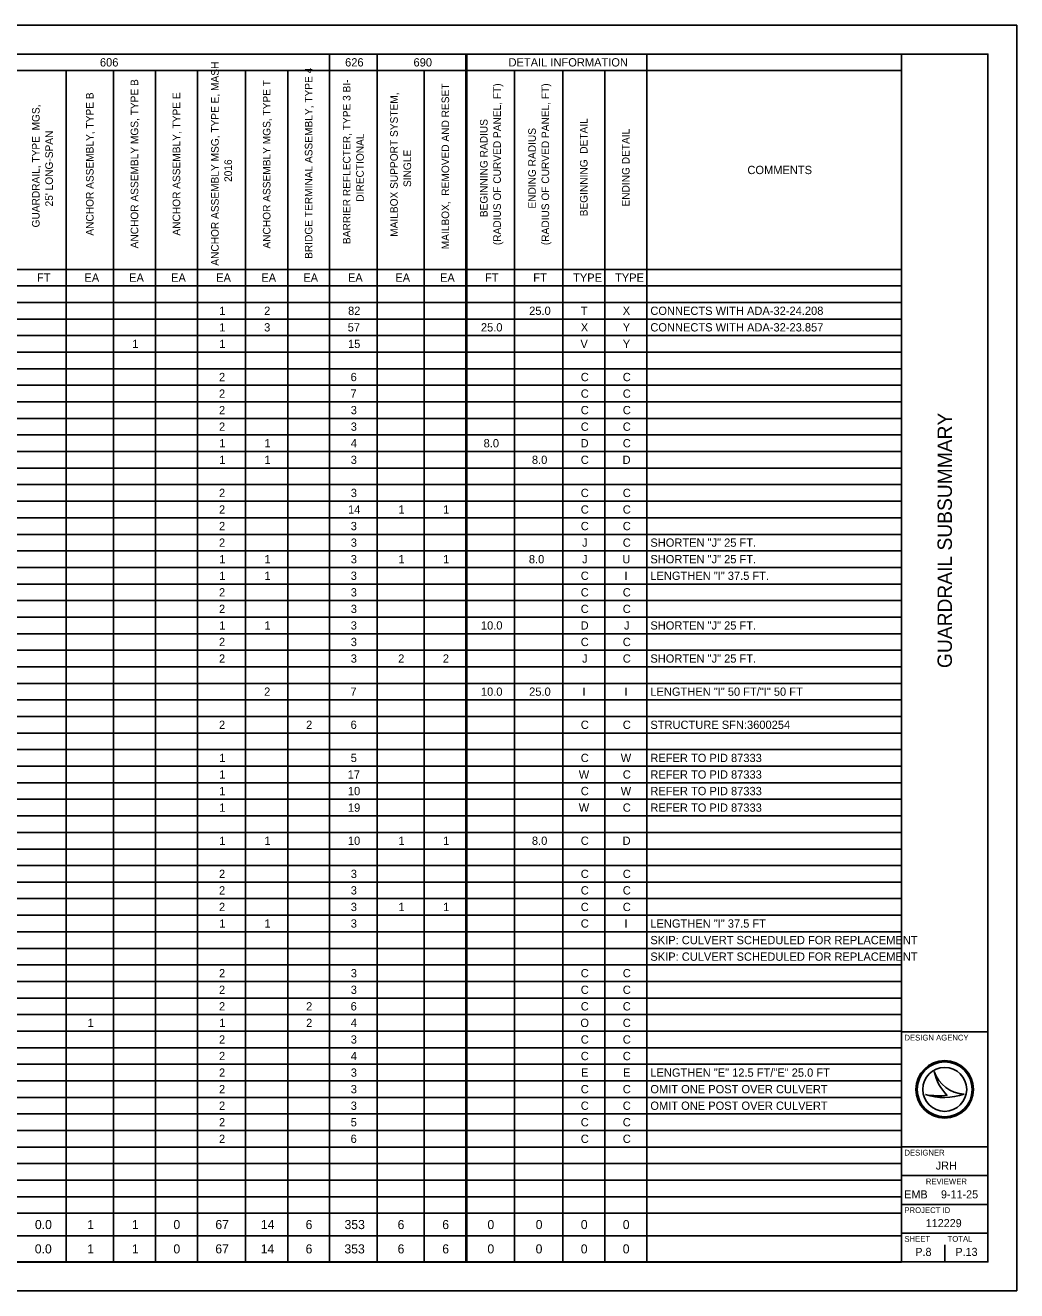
# Model space of a CAD drawing. Extents: x 0 to 34, y 0 to 22.
# Drawn here: x 16.78 to 34, y 0 to 22 of the extents above; entities that cross this region are included whole.
import ezdxf

# ---------------------------------------------------------------- set-up
doc = ezdxf.new("R2010")
doc.units = 0
for name, color, linetype in [('Default', 7, 'Continuous'), ('SH_Border', 7, 'Continuous'), ('SH_Cut_Line', 7, 'Continuous'), ('SH_Data', 7, 'Continuous')]:
    doc.layers.add(name, color=color, linetype=linetype)

msp = doc.modelspace()

# ---------------------------------------------------------------- linework, layer by layer
at = {"layer": 'Default'}
for p, q in [((1.5, 21.5), (24.449, 21.5)), ((22.064, 21.5), (22.064, 0.498)), ((22.887, 21.5), (22.887, 0.498)), ((24.428, 21.5), (31.997, 21.5)), ((24.428, 21.5), (24.428, 0.498)), ((24.449, 21.5), (24.449, 0.498)), ((27.574, 21.5), (27.574, 0.498)), ((31.997, 21.5), (31.997, 0.498)), ((5.582, 21.212), (24.428, 21.212)), ((17.486, 21.212), (17.486, 0.498)), ((18.308, 21.212), (18.308, 0.498)), ((19.038, 21.212), (19.038, 0.498)), ((19.767, 21.212), (19.767, 0.498)), ((20.605, 21.212), (20.605, 0.498)), ((21.335, 21.212), (21.335, 0.498)), ((23.709, 21.212), (23.709, 0.498)), ((24.449, 21.212), (31.997, 21.212)), ((25.277, 21.212), (25.277, 0.498)), ((26.115, 21.212), (26.115, 0.498)), ((26.844, 21.212), (26.844, 0.498)), ((5.582, 17.757), (24.428, 17.757)), ((24.449, 17.757), (31.997, 17.757)), ((1.5, 17.469), (24.428, 17.469)), ((24.449, 17.469), (31.997, 17.469)), ((1.5, 17.181), (24.428, 17.181)), ((24.449, 17.181), (31.997, 17.181)), ((1.5, 16.893), (24.428, 16.893)), ((24.449, 16.893), (31.997, 16.893)), ((1.5, 16.605), (24.428, 16.605)), ((24.449, 16.605), (31.997, 16.605)), ((1.5, 16.317), (24.428, 16.317)), ((24.449, 16.317), (31.997, 16.317)), ((1.5, 16.029), (24.428, 16.029)), ((24.449, 16.029), (31.997, 16.029)), ((1.5, 15.741), (24.428, 15.741)), ((24.449, 15.741), (31.997, 15.741)), ((1.5, 15.453), (24.428, 15.453)), ((24.449, 15.453), (31.997, 15.453)), ((1.5, 15.166), (24.428, 15.166)), ((24.449, 15.166), (31.997, 15.166)), ((1.5, 14.878), (24.428, 14.878)), ((24.449, 14.878), (31.997, 14.878)), ((1.5, 14.59), (24.428, 14.59)), ((24.449, 14.59), (31.997, 14.59)), ((1.5, 14.302), (24.428, 14.302)), ((24.449, 14.302), (31.997, 14.302)), ((1.5, 14.014), (24.428, 14.014)), ((24.449, 14.014), (31.997, 14.014)), ((1.5, 13.726), (24.428, 13.726)), ((24.449, 13.726), (31.997, 13.726)), ((1.5, 13.438), (24.428, 13.438)), ((24.449, 13.438), (31.997, 13.438)), ((1.5, 13.15), (24.428, 13.15)), ((24.449, 13.15), (31.997, 13.15)), ((1.5, 12.862), (24.428, 12.862)), ((24.449, 12.862), (31.997, 12.862)), ((1.5, 12.574), (24.428, 12.574)), ((24.449, 12.574), (31.997, 12.574)), ((1.5, 12.286), (24.428, 12.286)), ((24.449, 12.286), (31.997, 12.286)), ((1.5, 11.998), (24.428, 11.998)), ((24.449, 11.998), (31.997, 11.998)), ((1.5, 11.71), (24.428, 11.71)), ((24.449, 11.71), (31.997, 11.71)), ((1.5, 11.422), (24.428, 11.422)), ((24.449, 11.422), (31.997, 11.422)), ((1.5, 11.135), (24.428, 11.135)), ((24.449, 11.135), (31.997, 11.135)), ((1.5, 10.847), (24.428, 10.847)), ((24.449, 10.847), (31.997, 10.847)), ((1.5, 10.559), (24.428, 10.559)), ((24.449, 10.559), (31.997, 10.559)), ((1.5, 10.271), (24.428, 10.271)), ((24.449, 10.271), (31.997, 10.271)), ((1.5, 9.983), (24.428, 9.983)), ((24.449, 9.983), (31.997, 9.983)), ((1.5, 9.695), (24.428, 9.695)), ((24.449, 9.695), (31.997, 9.695)), ((1.5, 9.407), (24.428, 9.407)), ((24.449, 9.407), (31.997, 9.407)), ((1.5, 9.119), (24.428, 9.119)), ((24.449, 9.119), (31.997, 9.119)), ((1.5, 8.831), (24.428, 8.831)), ((24.449, 8.831), (31.997, 8.831)), ((1.5, 8.543), (24.428, 8.543)), ((24.449, 8.543), (31.997, 8.543)), ((1.5, 8.255), (24.428, 8.255)), ((24.449, 8.255), (31.997, 8.255)), ((1.5, 7.967), (24.428, 7.967)), ((24.449, 7.967), (31.997, 7.967)), ((1.5, 7.679), (24.428, 7.679)), ((24.449, 7.679), (31.997, 7.679)), ((1.5, 7.391), (24.428, 7.391)), ((24.449, 7.391), (31.997, 7.391)), ((1.5, 7.103), (24.428, 7.103)), ((24.449, 7.103), (31.997, 7.103)), ((1.5, 6.816), (24.428, 6.816)), ((24.449, 6.816), (31.997, 6.816)), ((1.5, 6.528), (24.428, 6.528)), ((24.449, 6.528), (31.997, 6.528)), ((1.5, 6.24), (24.428, 6.24)), ((24.449, 6.24), (31.997, 6.24)), ((1.5, 5.952), (24.428, 5.952)), ((24.449, 5.952), (31.997, 5.952)), ((1.5, 5.664), (24.428, 5.664)), ((24.449, 5.664), (31.997, 5.664)), ((1.5, 5.376), (24.428, 5.376)), ((24.449, 5.376), (31.997, 5.376)), ((1.5, 5.088), (24.428, 5.088)), ((24.449, 5.088), (31.997, 5.088)), ((1.5, 4.8), (24.428, 4.8)), ((24.449, 4.8), (31.997, 4.8)), ((1.5, 4.512), (24.428, 4.512)), ((24.449, 4.512), (31.997, 4.512)), ((1.5, 4.224), (24.428, 4.224)), ((24.449, 4.224), (31.997, 4.224)), ((1.5, 3.936), (24.428, 3.936)), ((24.449, 3.936), (31.997, 3.936)), ((1.5, 3.648), (24.428, 3.648)), ((24.449, 3.648), (31.997, 3.648)), ((1.5, 3.36), (24.428, 3.36)), ((24.449, 3.36), (31.997, 3.36)), ((1.5, 3.072), (24.428, 3.072)), ((24.449, 3.072), (31.997, 3.072)), ((1.5, 2.785), (24.428, 2.785)), ((24.449, 2.785), (31.997, 2.785)), ((1.5, 2.497), (24.428, 2.497)), ((24.449, 2.497), (31.997, 2.497)), ((1.5, 2.209), (24.428, 2.209)), ((24.449, 2.209), (31.997, 2.209)), ((1.5, 1.921), (24.428, 1.921)), ((24.449, 1.921), (31.997, 1.921)), ((1.5, 1.633), (24.428, 1.633)), ((24.449, 1.633), (31.997, 1.633)), ((1.5, 1.345), (24.428, 1.345)), ((24.449, 1.345), (31.997, 1.345)), ((11.231, 0.955), (17.486, 0.955)), ((17.486, 0.955), (18.308, 0.955)), ((18.308, 0.955), (24.428, 0.955)), ((24.449, 0.955), (31.997, 0.955)), ((1.5, 0.498), (17.486, 0.498)), ((17.486, 0.498), (18.308, 0.498)), ((18.308, 0.498), (24.449, 0.498)), ((24.428, 0.498), (31.997, 0.498))]:
    msp.add_line(p, q, dxfattribs=at)
at = {"layer": 'SH_Border'}
for p, q in [((32, 0.5), (32, 21.5)), ((32, 4.5), (33.5, 4.5)), ((32, 2.5), (33.5, 2.5)), ((32, 2), (33.5, 2)), ((32, 1.5), (33.5, 1.5)), ((32, 1), (33.5, 1))]:
    msp.add_line(p, q, dxfattribs=at)
msp.add_lwpolyline([(1.5, 21.5), (33.5, 21.5), (33.5, 0.5), (1.5, 0.5)], close=True, dxfattribs=at)
at = {"layer": 'SH_Cut_Line'}
msp.add_lwpolyline([(0, 0), (34, 0), (34, 22), (0, 22)], close=True, dxfattribs=at)
at = {"layer": 'SH_Data'}
for p, q in [((32.567, 3.81), (32.567, 3.81)), ((32.417, 3.41), (32.417, 3.41)), ((32.75, 3.5), (32.75, 3.5)), ((33.087, 3.419), (33.087, 3.419)), ((32.375, 0.675), (32.375, 0.675)), ((32.75, 0.5), (32.75, 0.8))]:
    msp.add_line(p, q, dxfattribs=at)
for radius in [0.5, 0.477, 0.477, 0.382]:
    msp.add_circle((32.75, 3.5), radius, dxfattribs=at)
for centre, radius, start, end in [((33.116, 3.998), 0.58, 198.9257, 198.9319), ((33.347, 3.97), 0.796, 191.6379, 191.6421), ((33.116, 3.998), 0.58, 198.9319, 267.1657), ((33.347, 3.97), 0.796, 191.6421, 226.0947), ((32.739, 4.37), 1.013, 251.4576, 290.0832), ((32.648, 4.654), 1.266, 259.4964, 259.4995), ((32.739, 4.37), 1.013, 251.4527, 251.4576), ((32.648, 4.654), 1.266, 259.4995, 276.6672)]:
    msp.add_arc(centre, radius, start, end, dxfattribs=at)

# ---------------------------------------------------------------- texts
at = {"layer": 'Default'}
for s, height, p in [('606', 0.144, (18.073, 21.284)), ('626', 0.144, (22.333, 21.284)), ('690', 0.144, (23.521, 21.284)), ('DETAIL INFORMATION', 0.14396, (25.172, 21.284)), ('COMMENTS', 0.144, (29.322, 19.413)), ('FT', 0.144, (16.979, 17.541)), ('EA', 0.144, (17.804, 17.541)), ('EA', 0.144, (18.58, 17.541)), ('EA', 0.144, (19.309, 17.541)), ('EA', 0.144, (20.093, 17.541)), ('EA', 0.144, (20.877, 17.541)), ('EA', 0.144, (21.606, 17.541)), ('EA', 0.144, (22.382, 17.541)), ('EA', 0.144, (23.205, 17.541)), ('EA', 0.144, (23.981, 17.541)), ('FT', 0.144, (24.763, 17.541)), ('FT', 0.144, (25.601, 17.541)), ('TYPE', 0.144, (26.293, 17.541)), ('TYPE', 0.144, (27.022, 17.541)), ('1', 0.144, (20.147, 16.965)), ('2', 0.144, (20.926, 16.965)), ('82', 0.144, (22.384, 16.965)), ('25.0', 0.144, (25.53, 16.965)), ('T', 0.144, (26.427, 16.965)), ('X', 0.144, (27.156, 16.965)), ('CONNECTS WITH ADA-32-24.208', 0.14396, (27.636, 16.965)), ('1', 0.144, (20.147, 16.677)), ('3', 0.144, (20.926, 16.677)), ('57', 0.144, (22.378, 16.677)), ('25.0', 0.144, (24.692, 16.677)), ('X', 0.144, (26.427, 16.677)), ('Y', 0.144, (27.157, 16.677)), ('CONNECTS WITH ADA-32-23.857', 0.14396, (27.636, 16.677)), ('1', 0.144, (18.634, 16.389)), ('1', 0.144, (20.147, 16.389)), ('15', 0.144, (22.383, 16.389)), ('V', 0.144, (26.421, 16.389)), ('Y', 0.144, (27.157, 16.389)), ('2', 0.144, (20.142, 15.813)), ('6', 0.144, (22.428, 15.813)), ('C', 0.144, (26.427, 15.813)), ('C', 0.144, (27.157, 15.813)), ('2', 0.144, (20.142, 15.525)), ('7', 0.144, (22.425, 15.525)), ('C', 0.144, (26.427, 15.525)), ('C', 0.144, (27.157, 15.525)), ('2', 0.144, (20.142, 15.238)), ('3', 0.144, (22.431, 15.238)), ('C', 0.144, (26.427, 15.238)), ('C', 0.144, (27.157, 15.238)), ('2', 0.144, (20.142, 14.95)), ('3', 0.144, (22.431, 14.95)), ('C', 0.144, (26.427, 14.95)), ('C', 0.144, (27.157, 14.95)), ('1', 0.144, (20.147, 14.662)), ('1', 0.144, (20.931, 14.662)), ('4', 0.144, (22.431, 14.662)), ('8.0', 0.144, (24.739, 14.662)), ('D', 0.144, (26.424, 14.662)), ('C', 0.144, (27.157, 14.662)), ('1', 0.144, (20.147, 14.374)), ('1', 0.144, (20.931, 14.374)), ('3', 0.144, (22.431, 14.374)), ('8.0', 0.144, (25.578, 14.374)), ('C', 0.144, (26.427, 14.374)), ('D', 0.144, (27.153, 14.374)), ('2', 0.144, (20.142, 13.798)), ('3', 0.144, (22.431, 13.798)), ('C', 0.144, (26.427, 13.798)), ('C', 0.144, (27.157, 13.798)), ('2', 0.144, (20.142, 13.51)), ('14', 0.144, (22.384, 13.51)), ('1', 0.144, (23.259, 13.51)), ('1', 0.144, (24.035, 13.51)), ('C', 0.144, (26.427, 13.51)), ('C', 0.144, (27.157, 13.51)), ('2', 0.144, (20.142, 13.222)), ('3', 0.144, (22.431, 13.222)), ('C', 0.144, (26.427, 13.222)), ('C', 0.144, (27.157, 13.222)), ('2', 0.144, (20.142, 12.934)), ('3', 0.144, (22.431, 12.934)), ('J', 0.144, (26.45, 12.934)), ('C', 0.144, (27.157, 12.934)), ('SHORTEN "J" 25 FT.', 0.14396, (27.636, 12.934)), ('1', 0.144, (20.147, 12.646)), ('1', 0.144, (20.931, 12.646)), ('3', 0.144, (22.431, 12.646)), ('1', 0.144, (23.259, 12.646)), ('1', 0.144, (24.035, 12.646)), ('8.0', 0.144, (25.525, 12.646)), ('J', 0.144, (26.45, 12.646)), ('U', 0.144, (27.149, 12.646)), ('SHORTEN "J" 25 FT.', 0.14396, (27.636, 12.646)), ('1', 0.144, (20.147, 12.358)), ('1', 0.144, (20.931, 12.358)), ('3', 0.144, (22.431, 12.358)), ('C', 0.144, (26.427, 12.358)), ('I', 0.144, (27.186, 12.358)), ('LENGTHEN "I" 37.5 FT.', 0.14396, (27.636, 12.358)), ('2', 0.144, (20.142, 12.07)), ('3', 0.144, (22.431, 12.07)), ('C', 0.144, (26.427, 12.07)), ('C', 0.144, (27.157, 12.07)), ('2', 0.144, (20.142, 11.782)), ('3', 0.144, (22.431, 11.782)), ('C', 0.144, (26.427, 11.782)), ('C', 0.144, (27.157, 11.782)), ('1', 0.144, (20.147, 11.494)), ('1', 0.144, (20.931, 11.494)), ('3', 0.144, (22.431, 11.494)), ('10.0', 0.144, (24.692, 11.494)), ('D', 0.144, (26.424, 11.494)), ('J', 0.144, (27.179, 11.494)), ('SHORTEN "J" 25 FT.', 0.14396, (27.636, 11.494)), ('2', 0.144, (20.142, 11.207)), ('3', 0.144, (22.431, 11.207)), ('C', 0.144, (26.427, 11.207)), ('C', 0.144, (27.157, 11.207)), ('2', 0.144, (20.142, 10.919)), ('3', 0.144, (22.431, 10.919)), ('2', 0.144, (23.254, 10.919)), ('2', 0.144, (24.03, 10.919)), ('J', 0.144, (26.45, 10.919)), ('C', 0.144, (27.157, 10.919)), ('SHORTEN "J" 25 FT.', 0.14396, (27.636, 10.919)), ('2', 0.144, (20.926, 10.343)), ('7', 0.144, (22.425, 10.343)), ('10.0', 0.144, (24.692, 10.343)), ('25.0', 0.144, (25.53, 10.343)), ('I', 0.144, (26.456, 10.343)), ('I', 0.144, (27.186, 10.343)), ('LENGTHEN "I" 50 FT/"I" 50 FT', 0.14396, (27.636, 10.343)), ('2', 0.144, (20.142, 9.767)), ('2', 0.144, (21.655, 9.767)), ('6', 0.144, (22.428, 9.767)), ('C', 0.144, (26.427, 9.767)), ('C', 0.144, (27.157, 9.767)), ('STRUCTURE SFN:3600254', 0.14396, (27.636, 9.767)), ('1', 0.144, (20.147, 9.191)), ('5', 0.144, (22.43, 9.191)), ('C', 0.144, (26.427, 9.191)), ('W', 0.144, (27.121, 9.191)), ('REFER TO PID 87333', 0.14396, (27.636, 9.191)), ('1', 0.144, (20.147, 8.903)), ('17', 0.144, (22.378, 8.903)), ('W', 0.144, (26.392, 8.903)), ('C', 0.144, (27.157, 8.903)), ('REFER TO PID 87333', 0.14396, (27.636, 8.903)), ('1', 0.144, (20.147, 8.615)), ('10', 0.144, (22.381, 8.615)), ('C', 0.144, (26.427, 8.615)), ('W', 0.144, (27.121, 8.615)), ('REFER TO PID 87333', 0.14396, (27.636, 8.615)), ('1', 0.144, (20.147, 8.327)), ('19', 0.144, (22.382, 8.327)), ('W', 0.144, (26.392, 8.327)), ('C', 0.144, (27.157, 8.327)), ('REFER TO PID 87333', 0.14396, (27.636, 8.327)), ('1', 0.144, (20.147, 7.751)), ('1', 0.144, (20.931, 7.751)), ('10', 0.144, (22.381, 7.751)), ('1', 0.144, (23.259, 7.751)), ('1', 0.144, (24.035, 7.751)), ('8.0', 0.144, (25.578, 7.751)), ('C', 0.144, (26.427, 7.751)), ('D', 0.144, (27.153, 7.751)), ('2', 0.144, (20.142, 7.175)), ('3', 0.144, (22.431, 7.175)), ('C', 0.144, (26.427, 7.175)), ('C', 0.144, (27.157, 7.175)), ('2', 0.144, (20.142, 6.888)), ('3', 0.144, (22.431, 6.888)), ('C', 0.144, (26.427, 6.888)), ('C', 0.144, (27.157, 6.888)), ('2', 0.144, (20.142, 6.6)), ('3', 0.144, (22.431, 6.6)), ('1', 0.144, (23.259, 6.6)), ('1', 0.144, (24.035, 6.6)), ('C', 0.144, (26.427, 6.6)), ('C', 0.144, (27.157, 6.6)), ('1', 0.144, (20.147, 6.312)), ('1', 0.144, (20.931, 6.312)), ('3', 0.144, (22.431, 6.312)), ('C', 0.144, (26.427, 6.312)), ('I', 0.144, (27.186, 6.312)), ('LENGTHEN "I" 37.5 FT', 0.14396, (27.636, 6.312)), ('SKIP: CULVERT SCHEDULED FOR REPLACEMENT', 0.14396, (27.636, 6.024)), ('SKIP: CULVERT SCHEDULED FOR REPLACEMENT', 0.14396, (27.636, 5.736)), ('2', 0.144, (20.142, 5.448)), ('3', 0.144, (22.431, 5.448)), ('C', 0.144, (26.427, 5.448)), ('C', 0.144, (27.157, 5.448)), ('2', 0.144, (20.142, 5.16)), ('3', 0.144, (22.431, 5.16)), ('C', 0.144, (26.427, 5.16)), ('C', 0.144, (27.157, 5.16)), ('2', 0.144, (20.142, 4.872)), ('2', 0.144, (21.655, 4.872)), ('6', 0.144, (22.428, 4.872)), ('C', 0.144, (26.427, 4.872)), ('C', 0.144, (27.157, 4.872)), ('1', 0.144, (17.858, 4.584)), ('1', 0.144, (20.147, 4.584)), ('2', 0.144, (21.655, 4.584)), ('4', 0.144, (22.431, 4.584)), ('O', 0.144, (26.42, 4.584)), ('C', 0.144, (27.157, 4.584)), ('2', 0.144, (20.142, 4.296)), ('3', 0.144, (22.431, 4.296)), ('C', 0.144, (26.427, 4.296)), ('C', 0.144, (27.157, 4.296)), ('2', 0.144, (20.142, 4.008)), ('4', 0.144, (22.431, 4.008)), ('C', 0.144, (26.427, 4.008)), ('C', 0.144, (27.157, 4.008)), ('2', 0.144, (20.142, 3.72)), ('3', 0.144, (22.431, 3.72)), ('E', 0.144, (26.432, 3.72)), ('E', 0.144, (27.162, 3.72)), ('LENGTHEN "E" 12.5 FT/"E" 25.0 FT', 0.14396, (27.636, 3.72)), ('2', 0.144, (20.142, 3.432)), ('3', 0.144, (22.431, 3.432)), ('C', 0.144, (26.427, 3.432)), ('C', 0.144, (27.157, 3.432)), ('OMIT ONE POST OVER CULVERT', 0.14396, (27.636, 3.432)), ('2', 0.144, (20.142, 3.144)), ('3', 0.144, (22.431, 3.144)), ('C', 0.144, (26.427, 3.144)), ('C', 0.144, (27.157, 3.144)), ('OMIT ONE POST OVER CULVERT', 0.14396, (27.636, 3.144)), ('2', 0.144, (20.142, 2.857)), ('5', 0.144, (22.43, 2.857)), ('C', 0.144, (26.427, 2.857)), ('C', 0.144, (27.157, 2.857)), ('2', 0.144, (20.142, 2.569)), ('6', 0.144, (22.428, 2.569)), ('C', 0.144, (26.427, 2.569)), ('C', 0.144, (27.157, 2.569)), ('0.0', 0.1584, (16.944, 1.071)), ('1', 0.158, (17.854, 1.071)), ('1', 0.158, (18.63, 1.071)), ('0', 0.158, (19.35, 1.071)), ('67', 0.1584, (20.079, 1.071)), ('14', 0.1584, (20.869, 1.071)), ('6', 0.158, (21.647, 1.071)), ('353', 0.1584, (22.323, 1.071)), ('6', 0.158, (23.245, 1.071)), ('6', 0.158, (24.021, 1.071)), ('0', 0.158, (24.806, 1.071)), ('0', 0.158, (25.644, 1.071)), ('0', 0.158, (26.428, 1.071)), ('0', 0.158, (27.157, 1.071)), ('0.0', 0.1584, (16.942, 0.648)), ('1', 0.158, (17.854, 0.648)), ('1', 0.158, (18.629, 0.648)), ('0', 0.158, (19.35, 0.648)), ('67', 0.1584, (20.078, 0.648)), ('14', 0.1584, (20.867, 0.648)), ('6', 0.158, (21.647, 0.648)), ('353', 0.1584, (22.321, 0.648)), ('6', 0.158, (23.245, 0.648)), ('6', 0.158, (24.021, 0.648)), ('0', 0.158, (24.805, 0.648)), ('0', 0.158, (25.643, 0.648)), ('0', 0.158, (26.427, 0.648)), ('0', 0.158, (27.156, 0.648))]:
    msp.add_text(s, height=height, dxfattribs=at).set_placement(p)
for s, height, p in [('ANCHOR ASSEMBLY MSG, TYPE E, MASH ', 0.13192, (20.137, 17.82)), ('BRIDGE TERMINAL ASSEMBLY, TYPE 4', 0.13192, (21.765, 17.939)), ('ANCHOR ASSEMBLY MGS, TYPE B', 0.13192, (18.739, 18.122)), ('ANCHOR ASSEMBLY MGS, TYPE T', 0.13192, (21.036, 18.118)), ('BARRIER REFLECTER, TYPE 3 BI-', 0.13192, (22.426, 18.196)), ('MAILBOX,  REMOVED AND RESET', 0.13192, (24.14, 18.106)), ('(RADIUS OF CURVED PANEL, FT)', 0.13192, (25.039, 18.178)), ('(RADIUS OF CURVED PANEL, FT)', 0.13192, (25.877, 18.178)), ('ANCHOR ASSEMBLY, TYPE B', 0.13192, (17.963, 18.343)), ('ANCHOR ASSEMBLY, TYPE E', 0.13192, (19.468, 18.344)), ('MAILBOX SUPPORT SYSTEM, ', 0.13192, (23.248, 18.323)), ('GUARDRAIL, TYPE  MGS, ', 0.13192, (17.025, 18.486)), ('BEGINNING RADIUS ', 0.13192, (24.808, 18.665)), ('BEGINNING  DETAIL', 0.13192, (26.545, 18.679)), ("25' LONG-SPAN", 0.13192, (17.256, 18.851)), ('DIRECTIONAL', 0.13192, (22.657, 18.933)), ('ENDING RADIUS ', 0.13192, (25.646, 18.813)), ('ENDING DETAIL', 0.13192, (27.275, 18.849)), ('SINGLE', 0.1319, (23.479, 19.188)), ('2016', 0.1319, (20.367, 19.277))]:
    msp.add_text(s, height=height, rotation=90, dxfattribs=at).set_placement(p)
at = {"layer": 'SH_Data'}
msp.add_text('GUARDRAIL SUBSUMMARY', height=0.25, rotation=90, dxfattribs=at).set_placement((32.875, 10.825))
for s, height, p in [('DESIGN AGENCY', 0.1, (32.05, 4.35)), ('DESIGNER', 0.1, (32.05, 2.35)), ('JRH', 0.14, (32.595, 2.105)), ('REVIEWER', 0.1, (32.422, 1.85)), ('EMB', 0.14, (32.047, 1.605)), ('9-11-25', 0.14, (32.685, 1.605)), ('PROJECT ID', 0.1, (32.05, 1.35)), ('112229', 0.14, (32.42, 1.105)), ('SHEET', 0.1, (32.05, 0.85)), ('TOTAL', 0.1, (32.8, 0.85)), ('P.8', 0.14, (32.239, 0.605)), ('P.13', 0.14, (32.935, 0.605))]:
    msp.add_text(s, height=height, dxfattribs=at).set_placement(p)

doc.saveas('drawing.dxf')
